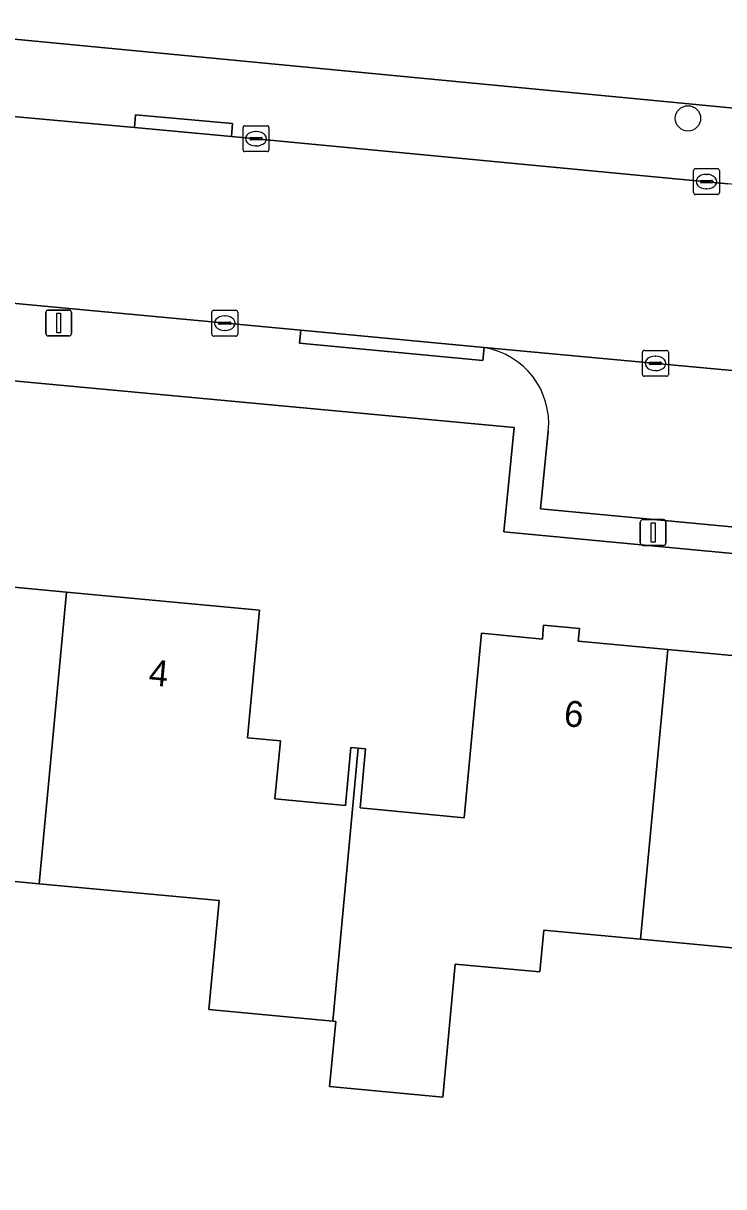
# Model space of a CAD drawing. Extents: x 162184 to 163154, y 385507 to 386516.
# Drawn here: x 162357.08 to 162384.14, y 385764.19 to 385809.15 of the extents above; entities that cross this region are included whole.
import ezdxf

# ---------------------------------------------------------------- set-up
doc = ezdxf.new("R2010")
doc.units = 0
for name, color, linetype in [('IMGEO_Boom', 7, 'Continuous'), ('IMGEO_Erf', 7, 'Continuous'), ('IMGEO_Kolk', 7, 'Continuous'), ('IMGEO_Lichtmast', 7, 'Continuous'), ('IMGEO_Pand', 7, 'Continuous'), ('IMGEO_Pand_nummerreeks', 7, 'Continuous'), ('IMGEO_Parkeervlak_open', 7, 'Continuous'), ('IMGEO_Rijbaan_lokaal_open', 7, 'Continuous'), ('IMGEO_Voetpad_open', 7, 'Continuous')]:
    doc.layers.add(name, color=color, linetype=linetype)

msp = doc.modelspace()

# ---------------------------------------------------------------- linework, layer by layer
at = {"layer": 'IMGEO_Boom'}
msp.add_circle((162382.758, 385805.474), 0.489, dxfattribs=at)
at = {"layer": 'IMGEO_Erf'}
for points in [[(162329.194, 385811.19), (162407.363, 385803.678), (162408.384, 385816.204), (162405.204, 385816.518), (162404.654, 385810.949), (162397.902, 385811.616), (162398.393, 385816.592), (162399.49, 385827.697), (162404.448, 385827.207), (162409.423, 385826.715), (162409.68, 385829.38), (162410.023, 385832.768), (162410.498, 385837), (162410.937, 385836.951), (162411.35, 385840.635), (162414.169, 385840.352), (162414.48, 385842.842), (162417.769, 385842.488), (162419.858, 385861.388), (162420.754, 385869.497), (162276.342, 385885.344)], [(162408.715, 385786.374), (162375.642, 385789.497), (162376.048, 385793.526), (162347.702, 385796.167)], [(162351.283, 385787.869), (162358.748, 385787.168), (162366.208, 385786.468), (162365.745, 385781.538), (162367.009, 385781.42), (162366.799, 385779.181), (162369.526, 385778.925), (162369.736, 385781.161), (162370.02, 385781.134), (162370.303, 385781.107), (162370.089, 385778.828), (162374.116, 385778.45), (162374.785, 385785.576), (162377.131, 385785.356), (162377.182, 385785.893), (162378.562, 385785.763), (162378.516, 385785.275), (162381.973, 385784.95), (162389.672, 385784.227)], [(162385.288, 385773.348), (162380.924, 385773.758), (162377.186, 385774.109), (162377.034, 385772.49), (162373.767, 385772.796), (162373.284, 385767.651), (162368.912, 385768.061), (162369.148, 385770.582), (162369.031, 385770.593), (162364.25, 385771.042), (162364.644, 385775.246), (162357.691, 385775.899), (162350.64, 385776.561), (162350.248, 385772.378), (162345.611, 385772.814), (162344.694, 385762.863), (162344.337, 385758.978), (162337.522, 385759.63), (162336.612, 385750), (162335.015, 385733.1)]]:
    msp.add_lwpolyline(points, dxfattribs=at)
at = {"layer": 'IMGEO_Kolk'}
for p, q in [((162365.568, 385804.264), (162365.568, 385805.116)), ((162365.643, 385805.19), (162366.495, 385805.19)), ((162366.569, 385805.116), (162366.569, 385804.264)), ((162365.827, 385804.684), (162365.827, 385804.696)), ((162366.265, 385804.647), (162365.867, 385804.647)), ((162365.87, 385804.733), (162366.268, 385804.733)), ((162366.056, 385804.97), (162366.081, 385804.97)), ((162366.311, 385804.696), (162366.311, 385804.684)), ((162366.495, 385804.19), (162365.643, 385804.19)), ((162366.079, 385804.41), (162366.054, 385804.41)), ((162382.973, 385802.606), (162382.973, 385803.458)), ((162383.048, 385803.532), (162383.9, 385803.532)), ((162383.461, 385803.312), (162383.486, 385803.312)), ((162383.974, 385803.458), (162383.974, 385802.606)), ((162383.232, 385803.026), (162383.232, 385803.038)), ((162383.67, 385802.989), (162383.272, 385802.989)), ((162383.275, 385803.075), (162383.673, 385803.075)), ((162383.716, 385803.038), (162383.716, 385803.026)), ((162383.9, 385802.532), (162383.048, 385802.532)), ((162383.484, 385802.752), (162383.459, 385802.752)), ((162364.362, 385797.133), (162364.362, 385797.985)), ((162364.437, 385798.059), (162365.289, 385798.059)), ((162365.363, 385797.985), (162365.363, 385797.133)), ((162364.621, 385797.553), (162364.621, 385797.565)), ((162365.059, 385797.516), (162364.661, 385797.516)), ((162364.664, 385797.602), (162365.062, 385797.602)), ((162364.85, 385797.839), (162364.875, 385797.839)), ((162365.105, 385797.565), (162365.105, 385797.553)), ((162365.289, 385797.059), (162364.437, 385797.059)), ((162364.873, 385797.279), (162364.848, 385797.279)), ((162380.998, 385795.582), (162380.998, 385796.434)), ((162381.073, 385796.508), (162381.925, 385796.508)), ((162381.486, 385796.288), (162381.511, 385796.288)), ((162381.999, 385796.434), (162381.999, 385795.582)), ((162381.257, 385796.002), (162381.257, 385796.014)), ((162381.695, 385795.965), (162381.297, 385795.965)), ((162381.3, 385796.051), (162381.698, 385796.051)), ((162381.509, 385795.728), (162381.484, 385795.728)), ((162381.741, 385796.014), (162381.741, 385796.002)), ((162381.925, 385795.508), (162381.073, 385795.508))]:
    msp.add_line(p, q, dxfattribs=at)
for points in [[(162365.568, 385804.264), (162365.568, 385805.116)], [(162365.643, 385805.19), (162366.495, 385805.19)], [(162366.569, 385805.116), (162366.569, 385804.264)], [(162366.495, 385804.19), (162365.643, 385804.19)], [(162382.973, 385802.606), (162382.973, 385803.458)], [(162383.048, 385803.532), (162383.9, 385803.532)], [(162383.974, 385803.458), (162383.974, 385802.606)], [(162383.9, 385802.532), (162383.048, 385802.532)], [(162364.362, 385797.133), (162364.362, 385797.985)], [(162364.437, 385798.059), (162365.289, 385798.059)], [(162365.363, 385797.985), (162365.363, 385797.133)], [(162365.289, 385797.059), (162364.437, 385797.059)], [(162380.998, 385795.582), (162380.998, 385796.434)], [(162381.073, 385796.508), (162381.925, 385796.508)], [(162381.999, 385796.434), (162381.999, 385795.582)], [(162381.925, 385795.508), (162381.073, 385795.508)]]:
    msp.add_lwpolyline(points, dxfattribs=at)
for centre, radius, start, end in [((162365.645, 385805.114), 0.0765, 91.552, 178.448), ((162365.645, 385805.114), 0.0765, 91.552, 178.448), ((162366.493, 385805.114), 0.0765, 1.552, 88.448), ((162366.493, 385805.114), 0.0765, 1.552, 88.448), ((162365.867, 385804.693), 0.0403, 85.8775, 175.7526), ((162365.864, 385804.683), 0.0366, 178.938, 274.7102), ((162366.268, 385804.69), 0.043, 264.8664, 352.4533), ((162366.272, 385804.695), 0.0386, 1.7309, 96.639), ((162365.645, 385804.266), 0.0765, 181.552, 268.448), ((162365.645, 385804.266), 0.0765, 181.552, 268.448), ((162366.493, 385804.266), 0.0765, 271.552, 358.448), ((162366.493, 385804.266), 0.0765, 271.552, 358.448), ((162383.05, 385803.456), 0.0765, 91.552, 178.448), ((162383.05, 385803.456), 0.0765, 91.552, 178.448), ((162383.898, 385803.456), 0.0765, 1.552, 88.448), ((162383.898, 385803.456), 0.0765, 1.552, 88.448), ((162383.272, 385803.035), 0.0403, 85.8775, 175.7526), ((162383.269, 385803.025), 0.0366, 178.938, 274.7102), ((162383.673, 385803.032), 0.043, 264.8664, 352.4533), ((162383.677, 385803.037), 0.0386, 1.7309, 96.639), ((162383.05, 385802.608), 0.0765, 181.552, 268.448), ((162383.05, 385802.608), 0.0765, 181.552, 268.448), ((162383.898, 385802.608), 0.0765, 271.552, 358.448), ((162383.898, 385802.608), 0.0765, 271.552, 358.448), ((162364.439, 385797.983), 0.0765, 91.552, 178.448), ((162364.439, 385797.983), 0.0765, 91.552, 178.448), ((162365.287, 385797.983), 0.0765, 1.552, 88.448), ((162365.287, 385797.983), 0.0765, 1.552, 88.448), ((162364.661, 385797.562), 0.0403, 85.8775, 175.7526), ((162364.658, 385797.552), 0.0366, 178.938, 274.7102), ((162365.062, 385797.559), 0.043, 264.8664, 352.4533), ((162365.066, 385797.564), 0.0386, 1.7309, 96.639), ((162364.439, 385797.135), 0.0765, 181.552, 268.448), ((162364.439, 385797.135), 0.0765, 181.552, 268.448), ((162365.287, 385797.135), 0.0765, 271.552, 358.448), ((162365.287, 385797.135), 0.0765, 271.552, 358.448), ((162381.075, 385796.432), 0.0765, 91.552, 178.448), ((162381.075, 385796.432), 0.0765, 91.552, 178.448), ((162381.923, 385796.432), 0.0765, 1.552, 88.448), ((162381.923, 385796.432), 0.0765, 1.552, 88.448), ((162381.297, 385796.011), 0.0403, 85.8775, 175.7526), ((162381.294, 385796.001), 0.0366, 178.938, 274.7102), ((162381.698, 385796.008), 0.043, 264.8664, 352.4533), ((162381.702, 385796.013), 0.0386, 1.7309, 96.639), ((162381.075, 385795.584), 0.0765, 181.552, 268.448), ((162381.075, 385795.584), 0.0765, 181.552, 268.448), ((162381.923, 385795.584), 0.0765, 271.552, 358.448), ((162381.923, 385795.584), 0.0765, 271.552, 358.448)]:
    msp.add_arc(centre, radius, start, end, dxfattribs=at)
for centre, major_axis, ratio, start_param, end_param in [((162366.055, 385804.69), (-0.387, 0.002), 0.722429, 4.712389, 7.853982), ((162366.08, 385804.69), (-0.39, 0.002), 0.717154, 1.570796, 4.712389), ((162383.46, 385803.032), (-0.387, 0.002), 0.722429, 4.712389, 7.853982), ((162383.485, 385803.032), (-0.39, 0.002), 0.717154, 1.570796, 4.712389), ((162364.849, 385797.559), (-0.387, 0.002), 0.722429, 4.712389, 7.853982), ((162364.874, 385797.559), (-0.39, 0.002), 0.717154, 1.570796, 4.712389), ((162381.485, 385796.008), (-0.387, 0.002), 0.722429, 4.712389, 7.853982), ((162381.51, 385796.008), (-0.39, 0.002), 0.717154, 1.570796, 4.712389)]:
    msp.add_ellipse(centre, major_axis=major_axis, ratio=ratio, start_param=start_param, end_param=end_param, dxfattribs=at)
at = {"layer": 'IMGEO_Lichtmast'}
for p, q in [((162357.95, 385797.168), (162357.95, 385797.968)), ((162357.95, 385797.968), (162357.95, 385797.168)), ((162358.05, 385798.068), (162358.84, 385798.068)), ((162358.84, 385798.068), (162358.05, 385798.068)), ((162358.94, 385797.968), (162358.94, 385797.168)), ((162358.94, 385797.168), (162358.94, 385797.968)), ((162358.84, 385797.068), (162358.05, 385797.068)), ((162358.05, 385797.068), (162358.84, 385797.068)), ((162380.914, 385789.07), (162380.914, 385789.87)), ((162380.914, 385789.87), (162380.914, 385789.07)), ((162381.014, 385789.97), (162381.804, 385789.97)), ((162381.804, 385789.97), (162381.014, 385789.97)), ((162381.904, 385789.87), (162381.904, 385789.07)), ((162381.904, 385789.07), (162381.904, 385789.87)), ((162381.804, 385788.97), (162381.014, 385788.97)), ((162381.014, 385788.97), (162381.804, 385788.97))]:
    msp.add_line(p, q, dxfattribs=at)
for points in [[(162358.37, 385797.943), (162358.52, 385797.943), (162358.52, 385797.193), (162358.37, 385797.193), (162358.37, 385797.943)], [(162381.334, 385789.845), (162381.484, 385789.845), (162381.484, 385789.095), (162381.334, 385789.095), (162381.334, 385789.845)]]:
    msp.add_lwpolyline(points, dxfattribs=at)
for centre, start, end in [((162358.05, 385797.968), 90, 180), ((162358.05, 385797.968), 90, 180), ((162358.84, 385797.968), 0, 90), ((162358.84, 385797.968), 360, 90), ((162358.05, 385797.168), 180, 270), ((162358.05, 385797.168), 180, 270), ((162358.84, 385797.168), 270, 0), ((162358.84, 385797.168), 270, 0), ((162381.014, 385789.87), 90, 180), ((162381.014, 385789.87), 90, 180), ((162381.804, 385789.87), 0, 90), ((162381.804, 385789.87), 360, 90), ((162381.014, 385789.07), 180, 270), ((162381.014, 385789.07), 180, 270), ((162381.804, 385789.07), 270, 0), ((162381.804, 385789.07), 270, 0)]:
    msp.add_arc(centre, 0.1, start, end, dxfattribs=at)
at = {"layer": 'IMGEO_Pand'}
for points in [[(162345.611, 385772.814), (162350.248, 385772.378), (162350.64, 385776.561), (162357.691, 385775.899), (162358.748, 385787.168), (162351.283, 385787.869), (162350.595, 385780.542), (162346.705, 385780.907), (162347.014, 385784.194), (162346.682, 385784.225)], [(162370.02, 385781.134), (162369.736, 385781.161), (162369.526, 385778.925), (162366.799, 385779.181), (162367.009, 385781.42), (162365.745, 385781.538), (162366.208, 385786.468), (162358.748, 385787.168), (162357.691, 385775.899), (162364.644, 385775.246), (162364.25, 385771.042), (162369.031, 385770.593)], [(162381.973, 385784.95), (162378.516, 385785.275), (162378.562, 385785.763), (162377.182, 385785.893), (162377.131, 385785.356), (162374.785, 385785.576), (162374.116, 385778.45), (162370.089, 385778.828), (162370.303, 385781.107), (162370.02, 385781.134), (162369.031, 385770.593), (162369.148, 385770.582), (162368.912, 385768.061), (162373.284, 385767.651), (162373.767, 385772.796), (162377.034, 385772.49), (162377.186, 385774.109), (162380.924, 385773.758)], [(162393.044, 385776.559), (162388.988, 385776.94), (162389.295, 385780.212), (162389.672, 385784.227), (162381.973, 385784.95), (162380.924, 385773.758), (162385.288, 385773.348), (162385.136, 385771.734), (162388.161, 385771.449), (162387.676, 385766.232), (162392.179, 385765.81), (162392.32, 385767.309), (162392.463, 385768.833)]]:
    msp.add_lwpolyline(points, close=True, dxfattribs=at)
at = {"layer": 'IMGEO_Parkeervlak_open'}
msp.add_lwpolyline([(162377.362, 385793.389), (162377.063, 385790.384), (162390.729, 385789.093), (162397.456, 385788.457), (162405.798, 385787.669), (162406.395, 385793.701), (162374.881, 385796.62)], dxfattribs=at)
msp.add_arc((162374.4, 385793.682), 2.977, 354.3436, 80.6958, dxfattribs=at)
at = {"layer": 'IMGEO_Rijbaan_lokaal_open'}
for points in [[(162403.08, 385801.118), (162388.077, 385802.582), (162384.303, 385802.95), (162365.118, 385804.775), (162361.369, 385805.117), (162345.728, 385806.544), (162344.013, 385806.701), (162341.355, 385806.833)], [(162344.775, 385799.544), (162347.581, 385799.237), (162351.413, 385798.818), (162367.799, 385797.286), (162374.881, 385796.62), (162406.395, 385793.701), (162406.599, 385795.822), (162406.652, 385796.366), (162407.054, 385800.73), (162403.08, 385801.118)]]:
    msp.add_lwpolyline(points, dxfattribs=at)
at = {"layer": 'IMGEO_Voetpad_open'}
for points in [[(162407.363, 385803.678), (162329.194, 385811.19)], [(162341.355, 385806.833), (162341.409, 385807.437), (162341.682, 385807.487), (162343.073, 385807.668), (162344.475, 385807.724), (162345.877, 385807.655), (162345.728, 385806.544), (162361.369, 385805.117), (162361.417, 385805.614), (162365.166, 385805.272), (162365.118, 385804.775), (162384.303, 385802.95)], [(162367.752, 385796.789), (162367.799, 385797.286), (162351.413, 385798.818), (162351.366, 385798.321), (162347.527, 385798.68), (162347.581, 385799.237), (162344.775, 385799.544)], [(162340.478, 385798.009), (162344.925, 385796.426), (162347.702, 385796.167), (162376.048, 385793.526), (162375.642, 385789.497), (162408.715, 385786.374), (162408.81, 385787.384), (162405.798, 385787.669), (162397.456, 385788.457), (162397.409, 385787.96), (162390.682, 385788.596), (162390.729, 385789.093), (162377.063, 385790.384), (162377.362, 385793.389)], [(162374.881, 385796.62), (162374.833, 385796.12), (162367.752, 385796.789)]]:
    msp.add_lwpolyline(points, dxfattribs=at)
for points in [[(162365.118, 385804.775), (162365.166, 385805.272), (162361.417, 385805.614), (162361.369, 385805.117)], [(162374.881, 385796.62), (162367.799, 385797.286), (162367.752, 385796.789), (162374.833, 385796.12)]]:
    msp.add_lwpolyline(points, close=True, dxfattribs=at)
msp.add_arc((162374.4, 385793.682), 2.977, 354.3436, 80.6958, dxfattribs=at)

# ---------------------------------------------------------------- texts
at = {"layer": 'IMGEO_Pand_nummerreeks'}
for s, rotation, p in [('4', 354.6374, (162361.897, 385783.579)), ('6', 354.8222, (162377.937, 385781.998))]:
    msp.add_text(s, height=1, rotation=rotation, dxfattribs=at).set_placement(p)

doc.saveas('drawing.dxf')
